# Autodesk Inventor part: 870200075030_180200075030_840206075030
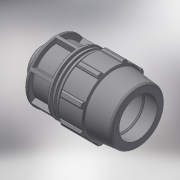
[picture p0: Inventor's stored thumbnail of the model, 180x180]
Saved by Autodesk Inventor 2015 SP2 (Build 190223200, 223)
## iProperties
Created: 2017-02
Part Number: 870200075030_180200075030_840206075030
Material: Generic
Description: PLASSON MALE ADAPTOR 75-3"
Document SubType Name: Modeling
Designer: KIM
Mass: 964.158 g
Surface Area: 1468.9 cm^2
Volume: 964.158 cm^3
Density: 1 g/cm^3
Appearance: Default
Author: KIM
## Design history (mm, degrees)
derived "87020.ipt"
feature "Solid1::87020.ipt"
tag "TaggingFeature1"
body "Solid1"
other parameters: "d2" = 75, "d4" = 28, "d5" = 49, "d7" = 132, "d8" = 99, "d9" = 28, "d11" = 5.6, "d12" = 105.6, "d13" = 120 deg, "d14" = 105, "d15" = 6 deg, "d16" = 118.8, "d18" = 3.75, "d19" = 35 deg, "d20" = 17.5 deg, "d21" = 122.76, "d23" = 0, "d25" = 360 deg, "d27" = 2.64, "d34" = 6.6, "d36" = 0, "d42" = 49, "d43" = 3.96, "d46" = 2.25, "d49" = 156, "d51" = 196, "d52" = 33, "d53" = 1.5, "d55" = 360 deg, "d57" = 87.884, "d58" = 61.5188, "d59" = 39.2, "d61" = 116.424, "d62" = 2.92, "d63" = 2.92, "d66" = 5.84, "d_" = 75, "E_" = 132, "H_" = 196, "l_" = 156, "l_2" = 33, "R_" = 87.884, "d60" = 14.6
